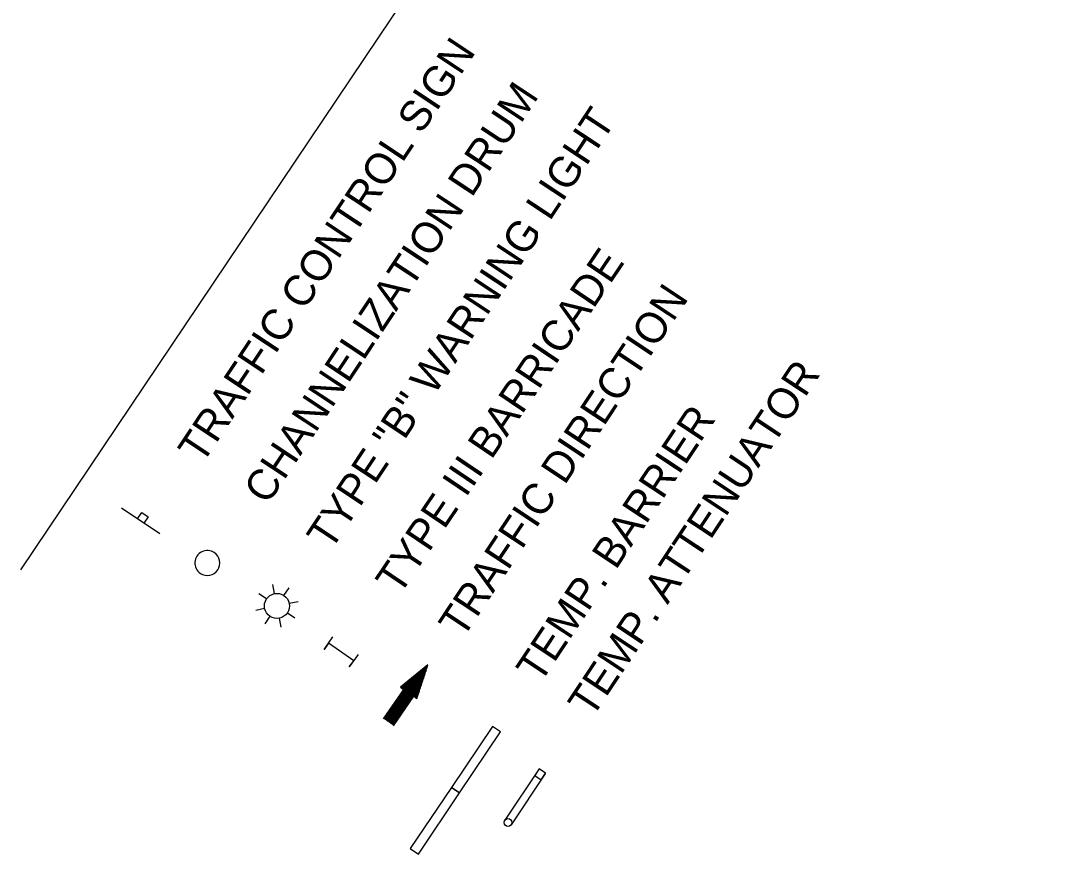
# Model space of a CAD drawing. Extents: x 1795987 to 1799689, y 243690 to 251545.
# Drawn here: x 1798590.9 to 1798856.3, y 248775.6 to 248987.7 of the extents above; entities that cross this region are included whole.
import ezdxf

# ---------------------------------------------------------------- set-up
doc = ezdxf.new("R2010")
doc.units = 0
doc.layers.add('LEGEND', color=7, linetype='Continuous')
doc.layers.add('Level 23', color=7, linetype='Continuous')

# ---------------------------------------------------------------- blocks, each defined once
blk = doc.blocks.new('T21LR')
at = {"layer": 'Level 23'}
for p, q in [((0, 2), (31.5, 2)), ((0, -2), (31.5, -2))]:
    blk.add_line(p, q, dxfattribs=at)
blk.add_lwpolyline([(0, -2), (4, -2), (4, 2), (0, 2)], close=True, dxfattribs=at)
blk.add_circle((31.5, 0), 2, dxfattribs=at)

msp = doc.modelspace()

# ---------------------------------------------------------------- linework, layer by layer
at = {"layer": 'LEGEND'}
for p, q in [((1798590.92, 248848), (1798856.3, 249243.25)), ((1798626.24, 248857.17), (1798616.52, 248863.69)), ((1798655.45, 248841.95), (1798655, 248844.22)), ((1798653.41, 248840.59), (1798651.49, 248841.88)), ((1798657.84, 248841.47), (1798659.13, 248843.38)), ((1798661.47, 248839.88), (1798659.2, 248839.43)), ((1798650.66, 248837.75), (1798652.93, 248838.2)), ((1798654.28, 248836.16), (1798653, 248834.24)), ((1798658.72, 248837.03), (1798660.63, 248835.74)), ((1798657.13, 248833.41), (1798656.68, 248835.68)), ((1798694.48, 248823.8), (1798687.51, 248818.11)), ((1798691.63, 248815.26), (1798694.48, 248823.8)), ((1798688.28, 248817.57), (1798683.12, 248810.1)), ((1798687.51, 248818.11), (1798688.28, 248817.57)), ((1798685.69, 248808.32), (1798690.85, 248815.8)), ((1798690.85, 248815.8), (1798691.63, 248815.26))]:
    msp.add_line(p, q, dxfattribs=at)
for points in [[(1798620.57, 248860.98), (1798621.66, 248862.6), (1798623.28, 248861.51), (1798622.19, 248859.89)], [(1798712.95, 248806.77), (1798710.87, 248808.16), (1798700.42, 248792.6), (1798702.5, 248791.2)], [(1798702.5, 248791.2), (1798700.42, 248792.6), (1798689.97, 248777.03), (1798692.05, 248775.63)]]:
    msp.add_lwpolyline(points, close=True, dxfattribs=at)
for points in [[(1798676.7, 248826.47), (1798674.47, 248823.27), (1798675.58, 248824.87), (1798669.18, 248829.32), (1798668.07, 248827.72), (1798670.3, 248830.92)], [(1798693.49, 248822.99), (1798684.11, 248809.41)], [(1798694.21, 248823.58), (1798684.33, 248809.27)], [(1798694.3, 248823.25), (1798684.54, 248809.12)], [(1798690.59, 248820.62), (1798683.26, 248810.01)], [(1798691.31, 248821.21), (1798683.47, 248809.86)], [(1798692.04, 248821.81), (1798683.68, 248809.71)], [(1798692.76, 248822.4), (1798683.9, 248809.56)], [(1798694, 248822.36), (1798684.75, 248808.97)], [(1798693.7, 248821.47), (1798684.97, 248808.82)], [(1798693.41, 248820.59), (1798685.18, 248808.68)], [(1798689.86, 248820.03), (1798688.2, 248817.63)], [(1798693.11, 248819.7), (1798685.39, 248808.53)], [(1798692.81, 248818.81), (1798685.61, 248808.38)], [(1798687.69, 248818.26), (1798687.56, 248818.07)], [(1798688.41, 248818.85), (1798687.77, 248817.92)], [(1798689.14, 248819.44), (1798687.99, 248817.77)], [(1798692.52, 248817.92), (1798690.98, 248815.7)], [(1798692.22, 248817.04), (1798691.2, 248815.56)], [(1798691.92, 248816.15), (1798691.41, 248815.41)]]:
    msp.add_lwpolyline(points, dxfattribs=at)
msp.add_circle((1798656.06, 248838.81), 3.19, dxfattribs=at)
for start, end in [(56.1222, 236.1222), (236.1222, 56.1222)]:
    msp.add_arc((1798638.35, 248849.73), 3.18, start, end, dxfattribs=at)

# ---------------------------------------------------------------- block references
at = {"layer": 'LEGEND', "xscale": 0.5000000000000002, "yscale": 0.5000000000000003, "rotation": -123.72854882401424}
msp.add_blockref('T21LR', (1798723.57, 248796.79), dxfattribs=at)

# ---------------------------------------------------------------- texts
at = {"layer": 'LEGEND'}
for s, rotation, p in [('TRAFFIC CONTROL SIGN', 56.4352, (1798637, 248874.59)), ('CHANNELIZATION DRUM', 56.4352, (1798653.67, 248864.29)), ('TYPE "B" WARNING LIGHT', 56.4352, (1798669.75, 248852.6)), ('TYPE III BARRICADE', 55.9561, (1798687.23, 248841.23)), ('TRAFFIC DIRECTION', 56.4352, (1798703.3, 248830.24)), ('TEMP. ATTENUATOR', 56.4352, (1798736.19, 248810.01)), ('TEMP. BARRIER', 56.4352, (1798723.01, 248818.79))]:
    msp.add_text(s, height=7.7999, rotation=rotation, dxfattribs=at).set_placement(p)

doc.saveas('drawing.dxf')
